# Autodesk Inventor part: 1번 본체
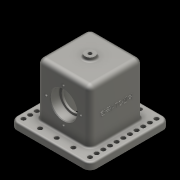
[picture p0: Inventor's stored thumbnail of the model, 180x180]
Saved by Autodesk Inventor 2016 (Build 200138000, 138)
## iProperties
Created: 2018-11
Part Number: 1번 본체
Material: 알루미늄 6061
Document SubType Name: Modeling
Designer: PC-16
Density: 2.7 g/cm^3
Appearance: 알루미늄 - 평지
Author: PC-16
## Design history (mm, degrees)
sketch "스케치1"
  geometry: L1 (-60, 60)-(60, 60); L2 (60, 60)-(60, -60); L3 (60, -60)-(-60, -60); L4 (-60, -60)-(-60, 60); L5 (-60, 60)-(60, -60); L6 (60, 60)-(-60, -60); 1 further point
  constraints: 12 end point, 2 midpoint, 2 parallel, 1 horizontal, 1 perpendicular
  dimensions: "d0" = 120 distance of L1.start L1.end; "d1" = 120 distance of L3.end L1.start
extrude "돌출1" new body sketch "스케치1" distance "d2" = 10; taper "d3" = 0 deg
sketch "스케치2"
  geometry: L1 (-40, 40)-(40, 40); L2 (40, 40)-(40, -40); L3 (40, -40)-(-40, -40); L4 (-40, -40)-(-40, 40); L5 (-40, 40)-(40, -40); L6 (40, 40)-(-40, -40); 1 further point
  constraints: 12 end point, 2 midpoint, 2 parallel, 1 horizontal, 1 perpendicular
  dimensions: "d4" = 80 distance of L2.end L3.end; "d5" = 80 distance of L1.end L2.end
extrude "돌출2" join sketch "스케치2" distance "d6" = 80; taper "d7" = 0 deg
sketch "스케치3"
  geometry: L1 (30, -23)-(-30, -23); L2 (-30, -23)-(-30, 23); L3 (-30, 23)-(30, 23); L4 (30, 23)-(30, -23); L5 (30, -23)-(-30, 23); L6 (-30, -23)-(30, 23); 1 further point
  constraints: 12 end point, 2 midpoint, 2 parallel, 1 horizontal, 1 perpendicular
  dimensions: "d8" = 60 distance of L1.start L1.end; "d9" = 46 distance of L3.end L1.start
extrude "돌출3" cut sketch "스케치3" distance "d10" = 80; taper "d11" = 0 deg
node "작업 평면1"
sketch "스케치4"
  geometry: L1 (-60, 0)-(60, 0) reference; L2 (-75.754, 48)-(75.754, 48); L3 (-40, 68)-(-26, 68); L4 (-26, 68)-(-26, 64.5); L5 (-26, 64.5)-(26, 64.5); L6 (26, 64.5)-(26, 68); L7 (26, 68)-(40, 68); L8 (-23, 0)-(-23, 80) reference; L9 (23, 0)-(23, 80) reference; L10 (-40, 10)-(-40, 90) reference; L11 (-40, 68)-(-40, 48); L12 (-40, 48)-(40, 48); L13 (40, 48)-(40, 68); L14 (40, 10)-(40, 90) reference; 4 further points
  constraints: 18 end point, 5 perpendicular, 3 midpoint, 2 horizontal, 2 point on line, 2 vertical alignment, 1 collinear
  dimensions: "d13" = 48 distance of point (0, 48) point (0, 0); "d14" = 40 diameter of L3 L2; "d16" = 33 diameter of L5 L2; "d17" = 40 diameter of L7 L2; "d18" = 14 distance of L6.end L7.end; "d19" = 14 distance of L3.start L3.end; "d20" = 3 horizontal distance of L8.end L4.end; "d21" = 3 horizontal distance of L5.end L9.end (derived)
revolve "회전1" sketch "스케치4" stored, may be unused: angle "d22" = 90 deg
sketch "스케치5"
  geometry: L1 (40, 40)-(-40, 40) reference; L2 (-40, 40)-(-40, -40) reference; L3 (-40, -40)-(40, -40) reference; L4 (40, -40)-(40, 40) reference; C1 r 7.5 at (0, 0); 1 further point
  constraints: 1 centre point, 1 coincident
  dimensions: "d23" = 15 diameter of C1
extrude "돌출4" join sketch "스케치5" distance "d24" = 5; taper "d25" = 0 deg
sketch "스케치6" dims "d26" = 52
  geometry: L1 (40, 38)-(40, 98.362); L2 (100, -10)-(-20, -10) reference; C1 r 20 at (40, 38) reference; C2 r 16.5 at (40, 38) reference; 3 further points
  constraints: 2 end point, 2 point on line, 2 vertical alignment, 1 coincident, 1 midpoint, 1 vertical, 2 other
hole "구멍1" sketch "스케치6" at (40, 64) diameter "d27" = 3.459; stored, may be unused: countersink angle "d31" = 90 deg, drill point angle "d33" = 120 deg; dims "d28" = 8, "d29" = 4, "d30" = 2, "d32" = 10.8
sketch "스케치7"
  geometry: C1 r 7.5 at (0, 0) reference; 2 further points
  constraints: 1 coincident
hole "구멍2" sketch "스케치7" at (0, 0) diameter "d37" = 5.459; stored, may be unused: countersink angle "d41" = 90 deg, drill point angle "d43" = 0 deg; dims "d38" = 12, "d39" = 4, "d40" = 2, "d42" = 14.8
fillet "모깎기1" dims "d44" = 10
sketch "스케치8"
  geometry: L1 (-50, -60)-(50, -60) reference; L2 (60, -50)-(60, 50) reference; L3 (50, 60)-(-50, 60) reference; L4 (-60, 50)-(-60, -50) reference; L5 (40, 40)-(40, -40) reference; L6 (40, -40)-(-40, -40) reference; L7 (-40, -40)-(-40, 40) reference; L8 (-40, 40)-(40, 40) reference; L9 (40, 40)-(-40, 40) reference; L10 (-40, 40)-(-40, -40) reference; L11 (-40, -40)-(40, -40) reference; L12 (40, -40)-(40, 40) reference; L13 (40, -40)-(40, 40) reference; C1 r 7.5 at (0, 0) reference; A1 r 10 centre (-50, -50) between (-60, -50) and (-50, -60) reference; A2 r 10 centre (50, -50) between (50, -60) and (60, -50) reference; A3 r 10 centre (50, 50) between (60, 50) and (50, 60) reference; A4 r 10 centre (-50, 50) between (-50, 60) and (-60, 50) reference; 11 further points
  constraints: 6 vertical alignment, 5 horizontal alignment, 2 coincident
  dimensions: "d45" = 25 distance of point (50, 50) point (25, 50); "d46" = 25 distance of point (0, 50) point (25, 50); "d47" = 25 distance of point (-25, 50) A4.centre; "d48" = 25 distance of point (-25, 50) point (0, 50) (derived); "d49" = 50 distance of point (50, 50) point (50, 0) (derived); "d50" = 10 distance of point (50, 40) point (50, 50); "d51" = 10 distance of point (50, 30) point (50, 40); "d52" = 10 distance of point (50, 20) point (50, 30); "d53" = 10 distance of point (50, 10) point (50, 20); "d54" = 10 distance of point (50, 0) point (50, 10) (derived)
hole "구멍3" sketch "스케치8" at (50, 50), (25, 50), (0, 50), (-25, 50), (-50, 50), (50, 0), (50, 40), (50, 30), (50, 20), (50, 10) diameter "d55" = 6.6; stored, may be unused: countersink angle "d59" = 90 deg, drill point angle "d61" = 0 deg; dims "d56" = 12, "d57" = 4, "d58" = 2, "d60" = 14.8
fillet "모깎기2" dims "d62" = 8
fillet "모깎기3" dims "d63" = 8
fillet "모깎기4" dims "d64" = 3
fillet "모깎기5" dims "d65" = 3
fillet "모깎기6" dims "d66" = 3
fillet "모깎기7" dims "d67" = 0.6
chamfer "모따기1" distance "d68" = 1; stored, may be unused: second distance "d69" = 2, angle "d70" = 45 deg
sketch "스케치9"
  geometry: L1 (82, 82)-(82, -18) reference; 2 further points
  constraints: 1 other
  dimensions: "d71" = 48 distance from line of L1 point (34, 31.759)
feature "엠보싱1" sketch "스케치9" dims "d0" = 120, "d1" = 120, "d8" = 60, "d9" = 46, "d72" = 0.5, "d73" = 0
node "솔리드1"
pattern_circular "원형 패턴1" dims angle "d35" = 360 deg
mirror "대칭1"
mirror "대칭2"
mirror "대칭3"
node "투영된 루프1"
node "작업 평면2"
node "투영된 루프2"
node "투영된 루프3"
other parameters: "d12" = 0
